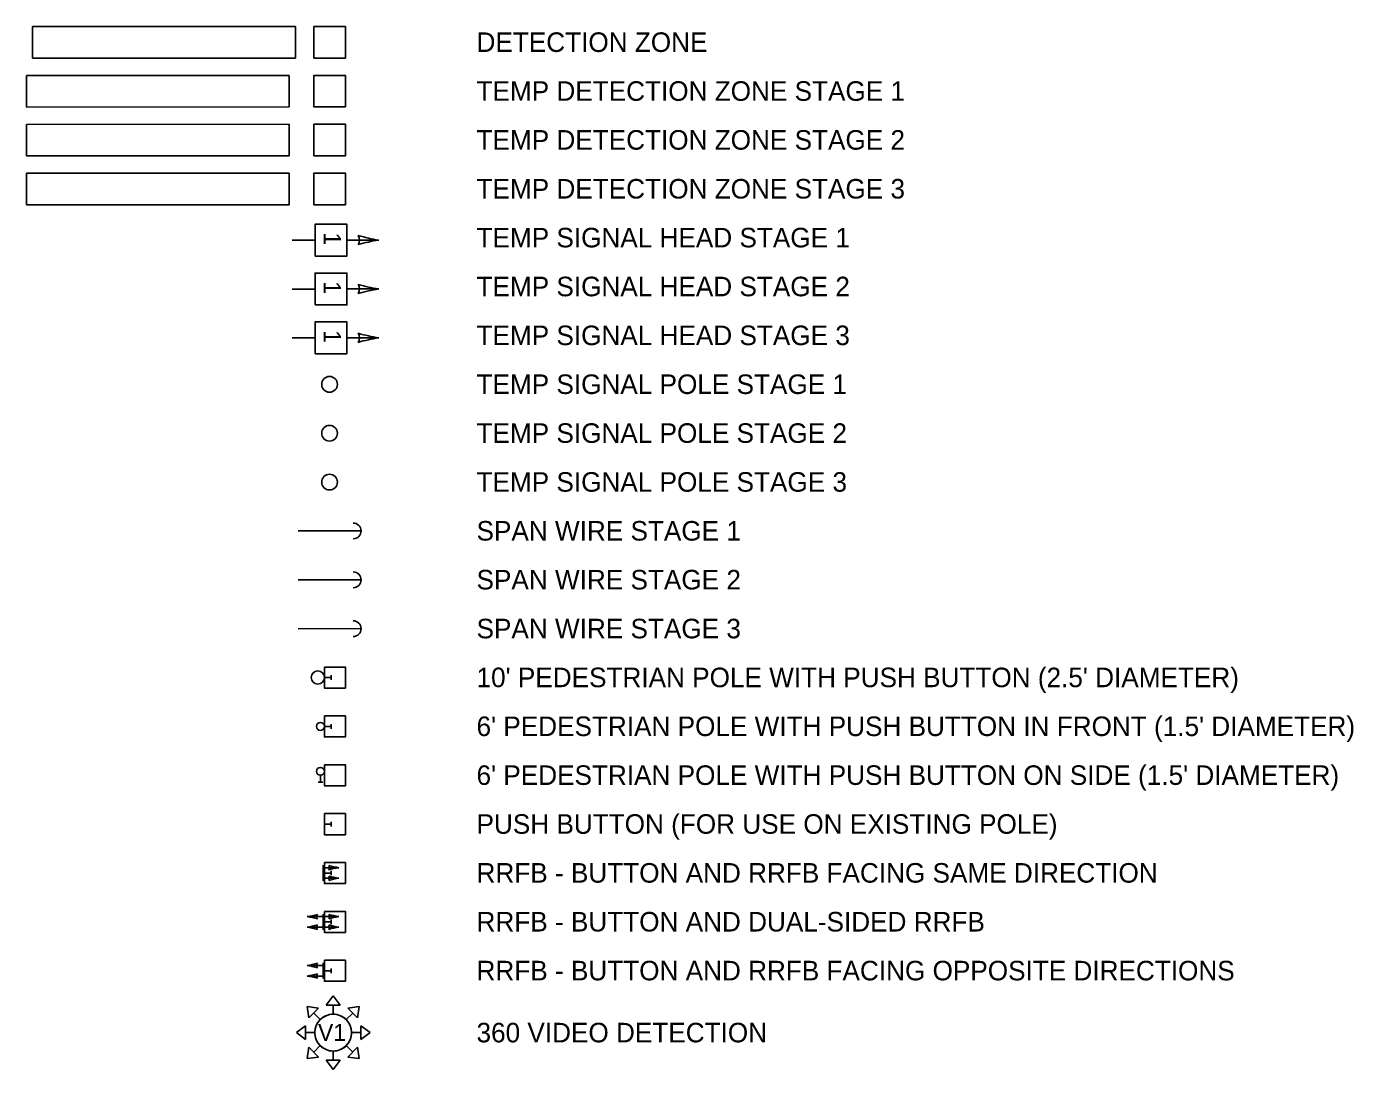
# Model space of a CAD drawing. Extents: x 995226 to 996234, y 1982095 to 1983315.
# Drawn here: x 995981.7 to 996234.2, y 1982912.7 to 1983111.2 of the extents above; entities that cross this region are included whole.
import ezdxf

# ---------------------------------------------------------------- set-up
doc = ezdxf.new("R2010")
doc.units = 0
for name, color, linetype in [('_CIVIL_CONSTRUCTION', 7, 'Continuous'), ('DSN_RDWY_Alignment Annotation', 7, 'Continuous'), ('DSN_ROW_Line-Annotation', 7, 'Continuous'), ('DSN_ROW_Point', 7, 'Continuous'), ('EX_ALIGNMENT', 7, 'Continuous'), ('EX_ROW', 7, 'Continuous'), ('S_EDGE_PAVEMENT', 7, 'Continuous'), ('S_HWY_SYMBOLS', 7, 'Continuous'), ('S_HWY_TEXT', 7, 'Continuous'), ('S_ORTHO_IMAGE', 7, 'Continuous'), ('S_PARKING', 7, 'Continuous'), ('S_PAVEMENT_CROWN', 7, 'Continuous'), ('S_SHOULDER', 7, 'Continuous'), ('S_SIDEWALK', 7, 'Continuous'), ('S_WALL_ANNOT', 7, 'Continuous')]:
    doc.layers.add(name, color=color, linetype=linetype)

msp = doc.modelspace()

# ---------------------------------------------------------------- linework, layer by layer
at = {"layer": '_CIVIL_CONSTRUCTION'}
for p, q in [((995981.68, 1983083.27), (996031.68, 1983083.29)), ((995981.68, 1983077.27), (995981.68, 1983083.27)), ((996031.68, 1983083.29), (996031.68, 1983077.29)), ((996031.68, 1983077.29), (995981.68, 1983077.27))]:
    msp.add_line(p, q, dxfattribs=at)
msp.add_lwpolyline([(996042.35, 1983077.29), (996036.35, 1983077.29), (996036.35, 1983083.29), (996042.35, 1983083.29)], close=True, dxfattribs=at)
at = {"layer": 'DSN_RDWY_Alignment Annotation'}
for p, q in [((996032.24, 1983061.22), (996036.59, 1983061.22)), ((996042.65, 1983061.25), (996048.69, 1983061.25))]:
    msp.add_line(p, q, dxfattribs=at)
msp.add_lwpolyline([(996036.59, 1983058.21), (996036.59, 1983064.27), (996042.65, 1983064.27), (996042.65, 1983058.21)], close=True, dxfattribs=at)
for centre, radius, start, end in [((996043.42, 1983061.25), 1.63, 328.1778, 31.8725), ((996053.09, 1983090.39), 29.47, 253.6787, 261.4168), ((996053.11, 1983032.11), 29.47, 98.6335, 106.3716)]:
    msp.add_arc(centre, radius, start, end, dxfattribs=at)
at = {"layer": 'DSN_ROW_Line-Annotation'}
for p, q in [((996032.24, 1983070.52), (996036.59, 1983070.52)), ((996042.65, 1983070.55), (996048.69, 1983070.55))]:
    msp.add_line(p, q, dxfattribs=at)
msp.add_lwpolyline([(996036.59, 1983067.51), (996036.59, 1983073.57), (996042.65, 1983073.57), (996042.65, 1983067.51)], close=True, dxfattribs=at)
for centre, radius, start, end in [((996043.42, 1983070.55), 1.63, 328.1778, 31.8725), ((996053.09, 1983099.69), 29.47, 253.6787, 261.4168), ((996053.11, 1983041.41), 29.47, 98.6335, 106.3716)]:
    msp.add_arc(centre, radius, start, end, dxfattribs=at)
at = {"layer": 'DSN_ROW_Point'}
for p, q in [((996032.24, 1983051.92), (996036.59, 1983051.92)), ((996042.65, 1983051.95), (996048.69, 1983051.95))]:
    msp.add_line(p, q, dxfattribs=at)
msp.add_lwpolyline([(996036.59, 1983048.91), (996036.59, 1983054.97), (996042.65, 1983054.97), (996042.65, 1983048.91)], close=True, dxfattribs=at)
for centre, radius, start, end in [((996043.42, 1983051.95), 1.63, 328.1778, 31.8725), ((996053.09, 1983081.09), 29.47, 253.6787, 261.4168), ((996053.11, 1983022.81), 29.47, 98.6335, 106.3716)]:
    msp.add_arc(centre, radius, start, end, dxfattribs=at)
at = {"layer": 'EX_ALIGNMENT'}
msp.add_line((996045.35, 1982996.6), (996033.35, 1982996.59), dxfattribs=at)
msp.add_circle((996039.34, 1983024.49), 1.5, dxfattribs=at)
msp.add_arc((996043.85, 1982996.6), 1.5, 270.0252, 90.0252, dxfattribs=at)
at = {"layer": 'EX_ROW'}
msp.add_line((996045.35, 1983005.9), (996033.35, 1983005.89), dxfattribs=at)
msp.add_circle((996039.34, 1983033.79), 1.5, dxfattribs=at)
msp.add_arc((996043.85, 1983005.9), 1.5, 270.0252, 90.0252, dxfattribs=at)
at = {"layer": 'S_EDGE_PAVEMENT'}
for p, q in [((996038.1, 1982951.59), (996038.1, 1982948.59)), ((996038.1, 1982951.09), (996041.12, 1982951.09)), ((996038.1, 1982950.22), (996038.1, 1982949.97)), ((996038.1, 1982950.22), (996038.35, 1982950.22)), ((996038.35, 1982949.97), (996038.1, 1982949.97)), ((996038.1, 1982949.09), (996041.12, 1982949.09)), ((996038.35, 1982949.97), (996038.35, 1982950.22)), ((996038.1, 1982941.79), (996035.08, 1982941.79)), ((996038.1, 1982942.29), (996038.1, 1982939.29)), ((996038.1, 1982941.79), (996041.12, 1982941.79)), ((996038.1, 1982939.79), (996035.08, 1982939.79)), ((996038.1, 1982940.92), (996038.1, 1982940.67)), ((996038.1, 1982940.92), (996038.35, 1982940.92)), ((996038.35, 1982940.67), (996038.1, 1982940.67)), ((996038.1, 1982939.79), (996041.12, 1982939.79)), ((996038.35, 1982940.67), (996038.35, 1982940.92)), ((996038.1, 1982932.49), (996035.08, 1982932.49)), ((996038.1, 1982932.99), (996038.1, 1982929.99)), ((996038.1, 1982931.62), (996038.1, 1982931.37)), ((996038.1, 1982931.62), (996038.35, 1982931.62)), ((996038.35, 1982931.37), (996038.1, 1982931.37)), ((996038.35, 1982931.37), (996038.35, 1982931.62)), ((996038.1, 1982930.49), (996035.08, 1982930.49))]:
    msp.add_line(p, q, dxfattribs=at)
for centre, radius in [((996039.34, 1983043.09), 1.5), ((996037.1, 1982987.3), 1.25), ((996037.6, 1982977.99), 0.75), ((996037.6, 1982969.44), 0.75)]:
    msp.add_circle(centre, radius, dxfattribs=at)
for centre, radius, start, end in [((996038.49, 1982951.09), 0.814, 328.1778, 31.8725), ((996043.32, 1982965.67), 14.74, 253.6787, 261.4168), ((996043.33, 1982936.53), 14.74, 98.6335, 106.3716), ((996038.49, 1982949.09), 0.814, 328.1778, 31.8725), ((996043.32, 1982963.67), 14.74, 253.6787, 261.4168), ((996043.34, 1982934.53), 14.74, 98.6335, 106.3716), ((996032.87, 1982956.36), 14.74, 278.6335, 286.3716), ((996032.88, 1982927.22), 14.74, 73.6787, 81.4168), ((996037.71, 1982941.79), 0.814, 148.1778, 211.8725), ((996038.49, 1982941.79), 0.814, 328.1778, 31.8725), ((996043.32, 1982956.37), 14.74, 253.6787, 261.4168), ((996043.33, 1982927.23), 14.74, 98.6335, 106.3716), ((996032.87, 1982954.36), 14.74, 278.6335, 286.3716), ((996032.88, 1982925.22), 14.74, 73.6787, 81.4168), ((996037.72, 1982939.79), 0.814, 148.1778, 211.8725), ((996038.49, 1982939.79), 0.814, 328.1778, 31.8725), ((996043.32, 1982954.37), 14.74, 253.6787, 261.4168), ((996043.34, 1982925.23), 14.74, 98.6335, 106.3716), ((996032.87, 1982947.06), 14.74, 278.6335, 286.3716), ((996032.88, 1982917.92), 14.74, 73.6787, 81.4168), ((996032.87, 1982945.06), 14.74, 278.6335, 286.3716), ((996037.71, 1982932.49), 0.814, 148.1778, 211.8725), ((996037.72, 1982930.49), 0.814, 148.1778, 211.8725), ((996032.88, 1982915.92), 14.74, 73.6787, 81.4168)]:
    msp.add_arc(centre, radius, start, end, dxfattribs=at)
at = {"layer": 'S_HWY_SYMBOLS'}
for p, q in [((995981.68, 1983092.57), (996031.68, 1983092.59)), ((995981.68, 1983086.57), (995981.68, 1983092.57)), ((996031.68, 1983092.59), (996031.68, 1983086.59)), ((996031.68, 1983086.59), (995981.68, 1983086.57))]:
    msp.add_line(p, q, dxfattribs=at)
msp.add_lwpolyline([(996042.35, 1983086.59), (996036.35, 1983086.59), (996036.35, 1983092.59), (996042.35, 1983092.59)], close=True, dxfattribs=at)
at = {"layer": 'S_HWY_TEXT'}
for p, q in [((995981.68, 1983101.87), (996031.68, 1983101.89)), ((995981.68, 1983095.87), (995981.68, 1983101.87)), ((996031.68, 1983101.89), (996031.68, 1983095.89)), ((996031.68, 1983095.89), (995981.68, 1983095.87))]:
    msp.add_line(p, q, dxfattribs=at)
msp.add_lwpolyline([(996042.35, 1983095.89), (996036.35, 1983095.89), (996036.35, 1983101.89), (996042.35, 1983101.89)], close=True, dxfattribs=at)
at = {"layer": 'S_ORTHO_IMAGE'}
msp.add_line((996045.35, 1983015.2), (996033.35, 1983015.19), dxfattribs=at)
msp.add_arc((996043.85, 1983015.2), 1.5, 270.0252, 90.0252, dxfattribs=at)
at = {"layer": 'S_PARKING'}
for p, q in [((995982.83, 1983111.17), (996032.83, 1983111.19)), ((995982.84, 1983105.17), (995982.83, 1983111.17)), ((996032.83, 1983111.19), (996032.84, 1983105.19)), ((996032.84, 1983105.19), (995982.84, 1983105.17))]:
    msp.add_line(p, q, dxfattribs=at)
msp.add_lwpolyline([(996042.35, 1983105.19), (996036.35, 1983105.19), (996036.35, 1983111.19), (996042.35, 1983111.19)], close=True, dxfattribs=at)
at = {"layer": 'S_PAVEMENT_CROWN'}
for p, q in [((996040.03, 1982926.72), (996038.72, 1982924.96)), ((996041.34, 1982924.96), (996040.03, 1982926.72)), ((996037.25, 1982924.35), (996035.07, 1982924.67)), ((996035.07, 1982924.67), (996035.39, 1982922.5)), ((996035.39, 1982922.5), (996037.25, 1982924.35)), ((996037.56, 1982922.19), (996036.32, 1982923.43)), ((996038.72, 1982924.96), (996041.34, 1982924.96)), ((996040.03, 1982923.21), (996040.03, 1982924.96)), ((996042.51, 1982922.19), (996043.74, 1982923.43)), ((996044.99, 1982924.67), (996042.82, 1982924.35)), ((996042.82, 1982924.35), (996044.67, 1982922.5)), ((996044.67, 1982922.5), (996044.99, 1982924.67)), ((996034.78, 1982921.02), (996033.02, 1982919.71)), ((996034.78, 1982918.4), (996034.78, 1982921.02)), ((996045.28, 1982921.03), (996045.28, 1982918.4)), ((996047.04, 1982919.71), (996045.28, 1982921.03)), ((996033.02, 1982919.71), (996034.78, 1982918.4)), ((996036.53, 1982919.71), (996034.78, 1982919.71)), ((996043.53, 1982919.71), (996045.28, 1982919.71)), ((996045.28, 1982918.4), (996047.04, 1982919.71)), ((996035.39, 1982916.93), (996035.08, 1982914.76)), ((996037.25, 1982915.07), (996035.39, 1982916.93)), ((996037.56, 1982917.24), (996036.32, 1982916)), ((996040.03, 1982916.21), (996040.03, 1982914.46)), ((996042.51, 1982917.24), (996043.75, 1982916)), ((996044.67, 1982916.93), (996042.82, 1982915.07)), ((996044.99, 1982914.76), (996044.67, 1982916.93)), ((996035.08, 1982914.76), (996037.25, 1982915.07)), ((996041.35, 1982914.46), (996038.72, 1982914.46)), ((996038.72, 1982914.46), (996040.03, 1982912.7)), ((996040.03, 1982912.7), (996041.35, 1982914.46)), ((996042.82, 1982915.07), (996044.99, 1982914.76))]:
    msp.add_line(p, q, dxfattribs=at)
msp.add_lwpolyline([(996037.35, 1982921.96), (996037.56, 1982922.19), (996037.78, 1982922.39), (996038.02, 1982922.58), (996038.28, 1982922.74), (996038.55, 1982922.88), (996038.83, 1982923), (996039.12, 1982923.09), (996039.42, 1982923.16), (996039.72, 1982923.2), (996040.03, 1982923.21), (996040.33, 1982923.2), (996040.64, 1982923.16), (996040.93, 1982923.09), (996041.23, 1982923), (996041.51, 1982922.89), (996041.78, 1982922.74), (996042.04, 1982922.58), (996042.28, 1982922.39), (996042.51, 1982922.19), (996042.71, 1982921.96), (996042.9, 1982921.72), (996043.06, 1982921.46), (996043.21, 1982921.19), (996043.32, 1982920.91), (996043.41, 1982920.62), (996043.48, 1982920.32), (996043.52, 1982920.02), (996043.53, 1982919.71), (996043.52, 1982919.41), (996043.48, 1982919.11), (996043.41, 1982918.81), (996043.32, 1982918.52), (996043.21, 1982918.23), (996043.07, 1982917.96), (996042.9, 1982917.71), (996042.72, 1982917.46), (996042.51, 1982917.24), (996042.28, 1982917.03), (996042.28, 1982917.03), (996042.04, 1982916.85), (996041.79, 1982916.68), (996041.51, 1982916.54), (996041.23, 1982916.42), (996040.94, 1982916.33), (996040.64, 1982916.27), (996040.34, 1982916.23), (996040.04, 1982916.21), (996039.73, 1982916.23), (996039.43, 1982916.26), (996039.13, 1982916.33), (996038.84, 1982916.42), (996038.56, 1982916.54), (996038.29, 1982916.68), (996038.03, 1982916.84), (996037.79, 1982917.03), (996037.56, 1982917.24), (996037.35, 1982917.46), (996037.17, 1982917.7), (996037, 1982917.96), (996036.86, 1982918.23), (996036.75, 1982918.51), (996036.65, 1982918.8), (996036.59, 1982919.1), (996036.55, 1982919.41), (996036.53, 1982919.71), (996036.55, 1982920.02), (996036.59, 1982920.32), (996036.65, 1982920.62), (996036.74, 1982920.91), (996036.86, 1982921.19), (996037, 1982921.46), (996037.17, 1982921.72)], close=True, dxfattribs=at)
msp.add_circle((996040.03, 1982919.71), 3.5, dxfattribs=at)
at = {"layer": 'S_SHOULDER'}
for points in [[(996038.35, 1982989.29), (996042.35, 1982989.29), (996042.35, 1982985.29), (996038.35, 1982985.29)], [(996038.35, 1982979.99), (996042.35, 1982979.99), (996042.35, 1982975.99), (996038.35, 1982975.99)], [(996038.35, 1982970.69), (996042.35, 1982970.69), (996042.35, 1982966.69), (996038.35, 1982966.69)], [(996038.35, 1982961.39), (996042.35, 1982961.39), (996042.35, 1982957.39), (996038.35, 1982957.39)], [(996038.35, 1982952.09), (996042.35, 1982952.09), (996042.35, 1982948.09), (996038.35, 1982948.09)], [(996038.35, 1982942.79), (996042.35, 1982942.79), (996042.35, 1982938.79), (996038.35, 1982938.79)], [(996038.35, 1982933.49), (996042.35, 1982933.49), (996042.35, 1982929.49), (996038.35, 1982929.49)]]:
    msp.add_lwpolyline(points, close=True, dxfattribs=at)
at = {"layer": 'S_SIDEWALK'}
for p, q in [((996038.35, 1982987.29), (996039.67, 1982987.29)), ((996039.67, 1982986.86), (996039.67, 1982987.73)), ((996038.35, 1982977.99), (996039.67, 1982977.99)), ((996039.67, 1982977.56), (996039.67, 1982978.43)), ((996037.17, 1982967.38), (996038.04, 1982967.37)), ((996037.6, 1982968.69), (996037.6, 1982967.37)), ((996038.35, 1982959.39), (996039.67, 1982959.39)), ((996039.67, 1982958.96), (996039.67, 1982959.83)), ((996038.35, 1982950.09), (996039.67, 1982950.09)), ((996039.67, 1982949.66), (996039.67, 1982950.53)), ((996039.67, 1982940.36), (996039.67, 1982941.23)), ((996038.35, 1982940.79), (996039.67, 1982940.79)), ((996038.35, 1982931.49), (996039.67, 1982931.49)), ((996039.67, 1982931.06), (996039.67, 1982931.93))]:
    msp.add_line(p, q, dxfattribs=at)

# ---------------------------------------------------------------- texts
at = {"layer": 'DSN_RDWY_Alignment Annotation'}
msp.add_text('1', height=3.25, rotation=270.0252, dxfattribs=at).set_placement((996038.24, 1983062.71))
at = {"layer": 'DSN_ROW_Line-Annotation'}
msp.add_text('1', height=3.25, rotation=270.0252, dxfattribs=at).set_placement((996038.24, 1983072.01))
at = {"layer": 'DSN_ROW_Point'}
msp.add_text('1', height=3.25, rotation=270.0252, dxfattribs=at).set_placement((996038.24, 1983053.41))
at = {"layer": 'S_PAVEMENT_CROWN'}
msp.add_text('V1', height=3.25, rotation=0.0252, dxfattribs=at).set_placement((996037.15, 1982918.12))
at = {"layer": 'S_WALL_ANNOT'}
for s, p in [('DETECTION ZONE', (996067.31, 1983106.36)), ('TEMP DETECTION ZONE STAGE 1', (996067.31, 1983097.06)), ('TEMP DETECTION ZONE STAGE 2', (996067.31, 1983087.76)), ('TEMP DETECTION ZONE STAGE 3', (996067.31, 1983078.46)), ('TEMP SIGNAL HEAD STAGE 1', (996067.31, 1983069.16)), ('TEMP SIGNAL HEAD STAGE 2', (996067.31, 1983059.86)), ('TEMP SIGNAL HEAD STAGE 3', (996067.31, 1983050.56)), ('TEMP SIGNAL POLE STAGE 1', (996067.31, 1983041.26)), ('TEMP SIGNAL POLE STAGE 2', (996067.31, 1983031.96)), ('TEMP SIGNAL POLE STAGE 3', (996067.31, 1983022.66)), ('SPAN WIRE STAGE 1', (996067.31, 1983013.36)), ('SPAN WIRE STAGE 2', (996067.31, 1983004.06)), ('SPAN WIRE STAGE 3', (996067.31, 1982994.76)), ("10' PEDESTRIAN POLE WITH PUSH BUTTON (2.5' DIAMETER)", (996067.31, 1982985.46)), ("6' PEDESTRIAN POLE WITH PUSH BUTTON IN FRONT (1.5' DIAMETER)", (996067.31, 1982976.16)), ("6' PEDESTRIAN POLE WITH PUSH BUTTON ON SIDE (1.5' DIAMETER)", (996067.31, 1982966.86)), ('PUSH BUTTON (FOR USE ON EXISTING POLE)', (996067.31, 1982957.56)), ('RRFB - BUTTON AND RRFB FACING SAME DIRECTION', (996067.31, 1982948.26)), ('RRFB - BUTTON AND DUAL-SIDED RRFB', (996067.31, 1982938.96)), ('RRFB - BUTTON AND RRFB FACING OPPOSITE DIRECTIONS', (996067.31, 1982929.66)), ('360 VIDEO DETECTION', (996067.31, 1982917.86))]:
    msp.add_text(s, height=3.72, dxfattribs=at).set_placement(p)

doc.saveas('drawing.dxf')
